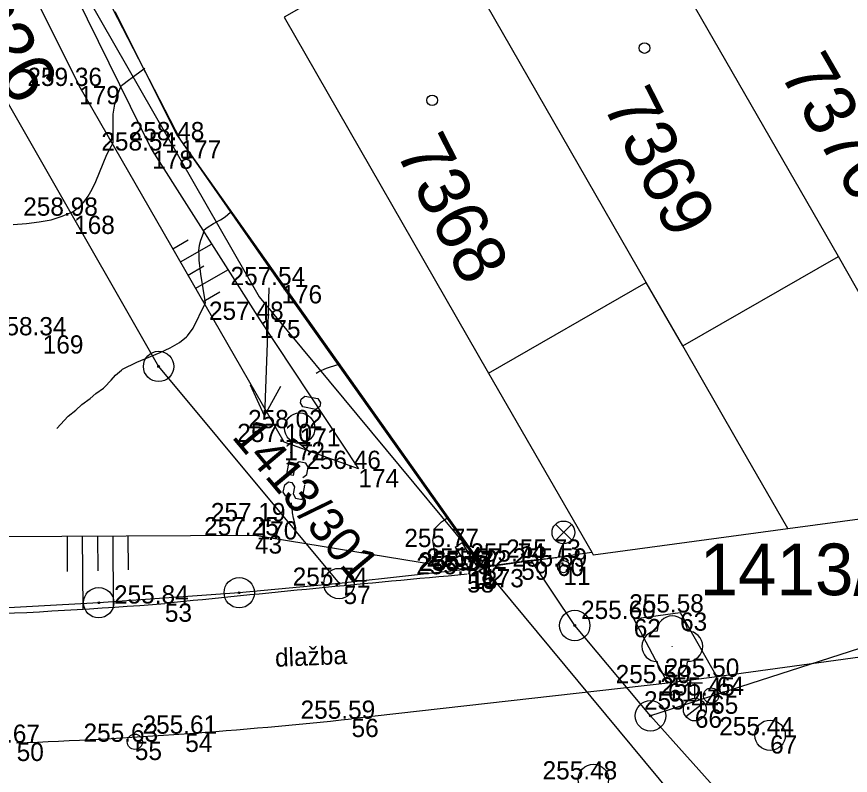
# Model space of a CAD drawing. Extents: x -771260 to -770828, y -1053564 to -1052811.
# Drawn here: x -770891.96 to -770864.55, y -1053372.8 to -1053347.85 of the extents above; entities that cross this region are included whole.
import ezdxf

# ---------------------------------------------------------------- set-up
doc = ezdxf.new("R2010")
doc.units = 0
for name, color, linetype in [('14_8_2023_asfalt', 7, 'Continuous'), ('14_8_2023_dlazba', 7, 'Continuous'), ('14_8_2023_hydrant_podzemni', 7, 'Continuous'), ('14_8_2023_lampa', 7, 'Continuous'), ('14_8_2023_plot', 7, 'Continuous'), ('14_8_2023_popis_povrchu', 7, 'Continuous'), ('14_8_2023_priska', 7, 'Continuous'), ('14_8_2023_sachta', 7, 'Continuous'), ('14_8_2023_soupe', 7, 'Continuous'), ('14_8_2023_strom', 7, 'Continuous'), ('14_8_2023_ter_hrana', 7, 'Continuous'), ('14_8_2023_ter_srafy', 7, 'Continuous'), ('14_8_2023_vstup_na_pozemek', 7, 'Continuous'), ('14_8_2023_zamereny_bod', 7, 'Continuous'), ('14_8_2023_zamereny_bod_cislo', 7, 'Continuous'), ('14_8_2023_zamereny_bod_vyska', 7, 'Continuous'), ('18_8_2023_plot', 7, 'Continuous'), ('18_8_2023_sachta', 7, 'Continuous'), ('18_8_2023_ter_hrana', 7, 'Continuous'), ('18_8_2023_ter_pata', 7, 'Continuous'), ('18_8_2023_ter_srafa', 7, 'Continuous'), ('18_8_2023_vrstevnice_po_1m', 7, 'Continuous'), ('18_8_2023_zamereny_bod', 7, 'Continuous'), ('18_8_2023_zamereny_bod_cislo', 7, 'Continuous'), ('18_8_2023_zamereny_bod_vyska', 7, 'Continuous'), ('DKM_Hranice parcel', 7, 'Continuous'), ('DKM_Parcelní čísla', 7, 'Continuous'), ('DKM_Pop  PČ popisy', 7, 'Continuous'), ('DKM_Vnitřní kresba', 7, 'Continuous'), ('DKM_Značky bodu BP', 7, 'Continuous'), ('DKM_Značky budov', 7, 'Continuous')]:
    doc.layers.add(name, color=color, linetype=linetype)

msp = doc.modelspace()

# ---------------------------------------------------------------- linework, layer by layer
at = {"layer": '14_8_2023_asfalt'}
msp.add_line((-770858.13, -1053368.076), (-770868.937, -1053369.555), dxfattribs=at)
at = {"layer": '14_8_2023_dlazba'}
for p, q in [((-770871.67, -1053367.654), (-770870.148, -1053367.441)), ((-770870.148, -1053367.441), (-770868.937, -1053369.555)), ((-770870.548, -1053369.768), (-770871.67, -1053367.654)), ((-770868.937, -1053369.555), (-770870.548, -1053369.768)), ((-770870.548, -1053369.768), (-770880.948, -1053370.937))]:
    msp.add_line(p, q, dxfattribs=at)
for centre, radius, start, end in [((-770800.804, -1054206.583), 843.858, 95.190639, 95.868492), ((-770900.926, -1053186.023), 181.652, 270.19912, 274.36998), ((-770897.564, -1053216.299), 155.529, 272.06585, 276.13275)]:
    msp.add_arc(centre, radius, start, end, dxfattribs=at)
at = {"layer": '14_8_2023_hydrant_podzemni'}
for p, q in [((-770869.912, -1053369.757), (-770869.412, -1053369.757)), ((-770869.662, -1053370.257), (-770869.662, -1053369.757)), ((-770869.956, -1053370.863), (-770869.366, -1053370.4))]:
    msp.add_line(p, q, dxfattribs=at)
msp.add_circle((-770869.662, -1053370.632), 0.375, dxfattribs=at)
at = {"layer": '14_8_2023_lampa'}
for p, q in [((-770874.246, -1053365.071), (-770873.718, -1053364.543)), ((-770873.71, -1053365.068), (-770874.238, -1053364.539)), ((-770873.982, -1053365.733), (-770873.982, -1053365.183))]:
    msp.add_line(p, q, dxfattribs=at)
for centre, radius in [((-770873.982, -1053364.808), 0.375), ((-770873.982, -1053365.933), 0.2)]:
    msp.add_circle(centre, radius, dxfattribs=at)
at = {"layer": '14_8_2023_plot'}
msp.add_line((-770876.674, -1053365.942), (-770875.371, -1053365.768), dxfattribs=at)
at = {"layer": '14_8_2023_priska'}
for p, q in [((-770877.541, -1053365.29), (-770877.311, -1053365.144)), ((-770877.541, -1053365.29), (-770877.046, -1053366.072)), ((-770876.816, -1053365.926), (-770877.311, -1053365.144)), ((-770877.046, -1053366.072), (-770876.816, -1053365.926))]:
    msp.add_line(p, q, dxfattribs=at)
at = {"layer": '14_8_2023_sachta'}
for centre in [(-770867.187, -1053371.48), (-770872.996, -1053372.932)]:
    msp.add_circle(centre, 0.5, dxfattribs=at)
at = {"layer": '14_8_2023_soupe'}
for centre in [(-770869.127, -1053370.173), (-770888.072, -1053371.693)]:
    msp.add_circle(centre, 0.25, dxfattribs=at)
at = {"layer": '14_8_2023_strom'}
msp.add_circle((-770870.404, -1053368.554), 0.0005, dxfattribs=at)
for centre, start, end in [((-770870.404, -1053368.054), 0, 180), ((-770870.904, -1053368.554), 90, 270), ((-770869.904, -1053368.554), 270, 90), ((-770870.404, -1053369.054), 180, 360)]:
    msp.add_arc(centre, 0.5, start, end, dxfattribs=at)
at = {"layer": '14_8_2023_ter_hrana'}
for p, q in [((-770884.123, -1053364.905), (-770897.467, -1053364.98)), ((-770877.079, -1053366.064), (-770884.123, -1053364.905))]:
    msp.add_line(p, q, dxfattribs=at)
at = {"layer": '14_8_2023_ter_srafy'}
for p, q in [((-770890.3, -1053364.939), (-770890.293, -1053366.098)), ((-770889.8, -1053364.936), (-770889.786, -1053367.333)), ((-770889.3, -1053364.934), (-770889.293, -1053366.067)), ((-770888.8, -1053364.931), (-770888.786, -1053367.269)), ((-770888.3, -1053364.928), (-770888.293, -1053366.036))]:
    msp.add_line(p, q, dxfattribs=at)
at = {"layer": '14_8_2023_vstup_na_pozemek'}
msp.add_line((-770874.194, -1053365.641), (-770875.371, -1053365.768), dxfattribs=at)
at = {"layer": '14_8_2023_zamereny_bod'}
for p, q in [((-770884.123, -1053364.905), (-770884.123, -1053364.905)), ((-770877.541, -1053365.29), (-770877.541, -1053365.29)), ((-770875.371, -1053365.768), (-770875.371, -1053365.768)), ((-770874.194, -1053365.641), (-770874.194, -1053365.641)), ((-770877.079, -1053366.064), (-770877.079, -1053366.064)), ((-770877.046, -1053366.072), (-770877.046, -1053366.072)), ((-770876.812, -1053365.934), (-770876.812, -1053365.934)), ((-770873.982, -1053365.933), (-770873.982, -1053365.933)), ((-770877.148, -1053366.185), (-770877.148, -1053366.185)), ((-770881.211, -1053366.564), (-770881.211, -1053366.564)), ((-770887.085, -1053367.147), (-770887.085, -1053367.147)), ((-770870.148, -1053367.441), (-770870.148, -1053367.441)), ((-770871.67, -1053367.654), (-770871.67, -1053367.654)), ((-770868.937, -1053369.555), (-770868.937, -1053369.555)), ((-770870.548, -1053369.768), (-770870.548, -1053369.768)), ((-770869.127, -1053370.173), (-770869.127, -1053370.173)), ((-770869.662, -1053370.632), (-770869.662, -1053370.632)), ((-770880.948, -1053370.937), (-770880.948, -1053370.937)), ((-770886.415, -1053371.427), (-770886.415, -1053371.427)), ((-770867.187, -1053371.48), (-770867.187, -1053371.48)), ((-770888.072, -1053371.693), (-770888.072, -1053371.693))]:
    msp.add_line(p, q, dxfattribs=at)
at = {"layer": '18_8_2023_plot'}
for p, q in [((-770889.236, -1053346.745), (-770886.57, -1053351.912)), ((-770886.57, -1053351.912), (-770883.254, -1053356.677)), ((-770883.254, -1053356.677), (-770876.674, -1053365.942))]:
    msp.add_line(p, q, dxfattribs=at)
at = {"layer": '18_8_2023_sachta'}
msp.add_circle((-770882.652, -1053361.381), 0.5, dxfattribs=at)
at = {"layer": '18_8_2023_ter_hrana'}
for p, q in [((-770894.318, -1053341.233), (-770889.903, -1053350.127)), ((-770883.159, -1053361.835), (-770889.903, -1053350.127)), ((-770880.721, -1053362.721), (-770883.159, -1053361.835))]:
    msp.add_line(p, q, dxfattribs=at)
at = {"layer": '18_8_2023_ter_pata'}
for p, q in [((-770887.502, -1053352.25), (-770890.436, -1053346.273)), ((-770887.502, -1053352.25), (-770883.963, -1053357.819)), ((-770883.963, -1053357.819), (-770880.721, -1053362.721))]:
    msp.add_line(p, q, dxfattribs=at)
at = {"layer": '18_8_2023_ter_srafa'}
for p, q in [((-770886.819, -1053355.48), (-770886.317, -1053355.191)), ((-770886.569, -1053355.913), (-770885.547, -1053355.324)), ((-770886.32, -1053356.346), (-770885.799, -1053356.047)), ((-770886.07, -1053356.78), (-770885.011, -1053356.169)), ((-770885.821, -1053357.213), (-770885.281, -1053356.902))]:
    msp.add_line(p, q, dxfattribs=at)
at = {"layer": '18_8_2023_vrstevnice_po_1m'}
for points in [[(-770892.071, -1053354.686), (-770891.633, -1053354.654), (-770891.216, -1053354.6), (-770890.82, -1053354.524), (-770890.459, -1053354.41), (-770890.254, -1053354.32), (-770890.145, -1053354.273), (-770890.105, -1053354.255), (-770890.061, -1053354.223), (-770889.877, -1053354.089), (-770889.748, -1053353.952), (-770889.602, -1053353.75), (-770889.473, -1053353.52), (-770889.355, -1053353.268), (-770888.988, -1053352.38), (-770888.843, -1053352.091), (-770888.807, -1053352.03), (-770888.782, -1053351.987), (-770888.784, -1053351.116), (-770888.784, -1053351.056), (-770888.731, -1053350.723), (-770888.665, -1053350.485), (-770888.567, -1053350.234), (-770888.529, -1053350.158), (-770888.506, -1053350.11), (-770888.241, -1053349.905), (-770888.208, -1053349.879), (-770887.781, -1053349.566), (-770887.746, -1053349.54)], [(-770887.746, -1053349.54), (-770887.746, -1053349.54)], [(-770887.746, -1053349.54), (-770887.746, -1053349.54)], [(-770888.208, -1053349.879), (-770888.208, -1053349.879)], [(-770888.506, -1053350.11), (-770888.506, -1053350.11)], [(-770888.665, -1053350.485), (-770888.665, -1053350.485)], [(-770888.567, -1053350.234), (-770888.567, -1053350.234)], [(-770888.731, -1053350.723), (-770888.731, -1053350.723)], [(-770888.784, -1053351.056), (-770888.784, -1053351.056)], [(-770888.843, -1053352.091), (-770888.843, -1053352.091)], [(-770888.782, -1053351.987), (-770888.782, -1053351.987)], [(-770888.988, -1053352.38), (-770888.988, -1053352.38)], [(-770889.355, -1053353.268), (-770889.355, -1053353.268)], [(-770889.602, -1053353.75), (-770889.602, -1053353.75)], [(-770889.473, -1053353.52), (-770889.473, -1053353.52)], [(-770889.748, -1053353.952), (-770889.748, -1053353.952)], [(-770890.64, -1053361.388), (-770890.259, -1053360.983), (-770890.011, -1053360.786), (-770889.815, -1053360.607), (-770889.542, -1053360.408), (-770889.352, -1053360.239), (-770889.103, -1053360.064), (-770889.065, -1053360.037), (-770888.846, -1053359.802), (-770888.712, -1053359.637), (-770888.512, -1053359.471), (-770888.475, -1053359.441), (-770888.007, -1053359.209), (-770887.235, -1053358.893), (-770886.907, -1053358.742), (-770886.602, -1053358.566), (-770886.374, -1053358.373), (-770886.339, -1053358.344), (-770886.16, -1053358.093), (-770885.767, -1053357.307), (-770885.744, -1053357.26), (-770885.901, -1053356.318), (-770885.954, -1053355.857), (-770885.959, -1053355.654), (-770885.963, -1053355.547), (-770885.945, -1053355.361), (-770885.906, -1053355.193), (-770885.82, -1053354.965), (-770885.806, -1053354.918), (-770885.79, -1053354.863), (-770885.697, -1053354.783), (-770885.481, -1053354.647), (-770885.295, -1053354.55), (-770885.253, -1053354.529), (-770885.101, -1053354.426), (-770884.922, -1053354.279), (-770884.888, -1053354.251)], [(-770890.105, -1053354.255), (-770890.105, -1053354.255)], [(-770889.877, -1053354.089), (-770889.877, -1053354.089)], [(-770884.888, -1053354.251), (-770884.888, -1053354.251)], [(-770884.888, -1053354.251), (-770884.888, -1053354.251)], [(-770891.216, -1053354.6), (-770891.216, -1053354.6)], [(-770890.82, -1053354.524), (-770890.82, -1053354.524)], [(-770890.459, -1053354.41), (-770890.459, -1053354.41)], [(-770885.253, -1053354.529), (-770885.253, -1053354.529)], [(-770885.101, -1053354.426), (-770885.101, -1053354.426)], [(-770891.633, -1053354.654), (-770891.633, -1053354.654)], [(-770885.79, -1053354.863), (-770885.79, -1053354.863)], [(-770885.697, -1053354.783), (-770885.697, -1053354.783)], [(-770885.481, -1053354.647), (-770885.481, -1053354.647)], [(-770885.82, -1053354.965), (-770885.82, -1053354.965)], [(-770885.945, -1053355.361), (-770885.945, -1053355.361)], [(-770885.906, -1053355.193), (-770885.906, -1053355.193)], [(-770885.963, -1053355.547), (-770885.963, -1053355.547)], [(-770885.954, -1053355.857), (-770885.954, -1053355.857)], [(-770885.901, -1053356.318), (-770885.901, -1053356.318)], [(-770885.744, -1053357.26), (-770885.744, -1053357.26)], [(-770886.16, -1053358.093), (-770886.16, -1053358.093)], [(-770886.339, -1053358.344), (-770886.339, -1053358.344)], [(-770886.602, -1053358.566), (-770886.602, -1053358.566)], [(-770887.235, -1053358.893), (-770887.235, -1053358.893)], [(-770886.907, -1053358.742), (-770886.907, -1053358.742)], [(-770888.007, -1053359.209), (-770888.007, -1053359.209)], [(-770888.475, -1053359.441), (-770888.475, -1053359.441)], [(-770882.114, -1053359.574), (-770882.056, -1053359.536), (-770882.021, -1053359.514), (-770881.775, -1053359.411), (-770881.397, -1053359.291), (-770881.353, -1053359.277)], [(-770882.021, -1053359.514), (-770882.021, -1053359.514)], [(-770881.775, -1053359.411), (-770881.775, -1053359.411)], [(-770888.846, -1053359.802), (-770888.846, -1053359.802)], [(-770888.712, -1053359.637), (-770888.712, -1053359.637)], [(-770882.114, -1053359.574), (-770882.114, -1053359.574)], [(-770889.065, -1053360.037), (-770889.065, -1053360.037)], [(-770889.352, -1053360.239), (-770889.352, -1053360.239)], [(-770881.99, -1053360.665), (-770882.119, -1053360.762), (-770882.547, -1053360.681), (-770882.631, -1053360.543), (-770882.609, -1053360.425), (-770882.479, -1053360.328), (-770882.052, -1053360.409), (-770881.967, -1053360.547), (-770881.99, -1053360.665)], [(-770889.815, -1053360.607), (-770889.815, -1053360.607)], [(-770889.542, -1053360.408), (-770889.542, -1053360.408)], [(-770890.011, -1053360.786), (-770890.011, -1053360.786)], [(-770890.259, -1053360.983), (-770890.259, -1053360.983)], [(-770890.64, -1053361.388), (-770890.64, -1053361.388)], [(-770882.124, -1053361.371), (-770882.231, -1053361.35)], [(-770882.945, -1053362.189), (-770882.855, -1053361.719), (-770882.281, -1053362.194)], [(-770882.544, -1053362.997), (-770882.415, -1053362.899), (-770882.37, -1053362.664), (-770882.455, -1053362.526), (-770882.669, -1053362.486), (-770882.798, -1053362.583), (-770882.865, -1053362.936), (-770883.079, -1053362.895), (-770882.989, -1053362.424)], [(-770883.106, -1053363.621), (-770883.191, -1053363.483), (-770883.146, -1053363.248), (-770883.017, -1053363.15), (-770882.91, -1053363.171), (-770882.825, -1053363.309), (-770882.87, -1053363.544), (-770882.786, -1053363.682), (-770882.572, -1053363.723), (-770882.482, -1053363.252)], [(-770882.806, -1053364.668), (-770882.816, -1053364.507), (-770882.856, -1053364.342), (-770882.886, -1053364.166), (-770882.898, -1053364.001), (-770882.923, -1053363.853), (-770882.926, -1053363.838)], [(-770882.898, -1053364.001), (-770882.898, -1053364.001)], [(-770882.886, -1053364.166), (-770882.886, -1053364.166)], [(-770882.856, -1053364.342), (-770882.856, -1053364.342)], [(-770878.164, -1053365.649), (-770878.183, -1053365.584), (-770878.27, -1053365.073), (-770878.215, -1053364.734), (-770878.206, -1053364.684), (-770877.99, -1053364.456), (-770877.891, -1053364.399), (-770877.814, -1053364.336), (-770877.78, -1053364.308)], [(-770877.99, -1053364.456), (-770877.99, -1053364.456)], [(-770877.891, -1053364.399), (-770877.891, -1053364.399)], [(-770877.78, -1053364.308), (-770877.78, -1053364.308)], [(-770877.78, -1053364.308), (-770877.78, -1053364.308)], [(-770882.816, -1053364.507), (-770882.816, -1053364.507)], [(-770882.806, -1053364.668), (-770882.806, -1053364.668)], [(-770878.206, -1053364.684), (-770878.206, -1053364.684)], [(-770878.27, -1053365.073), (-770878.27, -1053365.073)], [(-770878.183, -1053365.584), (-770878.183, -1053365.584)], [(-770878.164, -1053365.649), (-770878.164, -1053365.649)]]:
    msp.add_lwpolyline(points, dxfattribs=at)
at = {"layer": '18_8_2023_zamereny_bod'}
for p, q in [((-770889.903, -1053350.127), (-770889.903, -1053350.127)), ((-770886.57, -1053351.912), (-770886.57, -1053351.912)), ((-770887.502, -1053352.25), (-770887.502, -1053352.25)), ((-770890.068, -1053354.394), (-770890.068, -1053354.394)), ((-770883.254, -1053356.677), (-770883.254, -1053356.677)), ((-770883.963, -1053357.819), (-770883.963, -1053357.819)), ((-770891.101, -1053358.327), (-770891.101, -1053358.327)), ((-770882.652, -1053361.381), (-770882.652, -1053361.381)), ((-770883.159, -1053361.835), (-770883.159, -1053361.835)), ((-770880.721, -1053362.721), (-770880.721, -1053362.721)), ((-770884.067, -1053364.441), (-770884.067, -1053364.441)), ((-770876.623, -1053366.013), (-770876.623, -1053366.013))]:
    msp.add_line(p, q, dxfattribs=at)
at = {"layer": 'DKM_Hranice parcel'}
for p, q in [((-770891.21, -1053344.44), (-770883.99, -1053357.06)), ((-770886.69, -1053351.72), (-770888.72, -1053347.69)), ((-770876.6, -1053365.96), (-770886.69, -1053351.72)), ((-770883.99, -1053357.06), (-770876.6, -1053365.96)), ((-770841.15, -1053361.17), (-770871.12, -1053370.84)), ((-770866.61, -1053364.68), (-770860.3, -1053363.83)), ((-770875.03, -1053365.74), (-770873.05, -1053365.46)), ((-770875.03, -1053365.74), (-770876.6, -1053365.96)), ((-770876.6, -1053365.96), (-770881.36, -1053366.49)), ((-770865.26, -1053379.61), (-770876.6, -1053365.96))]:
    msp.add_line(p, q, dxfattribs=at)
for points in [[(-770902.17, -1053333.34), (-770887.29, -1053359.35), (-770881.36, -1053366.49)], [(-770877.98, -1053344.89), (-770883.16, -1053347.86), (-770876.44, -1053359.57), (-770873.05, -1053365.46)], [(-770860.3, -1053363.83), (-770862.54, -1053359.93), (-770863.75, -1053357.82), (-770864.94, -1053355.74), (-770870.47, -1053346.11)], [(-770866.61, -1053364.68), (-770868.29, -1053361.75), (-770870.06, -1053358.67), (-770871.26, -1053356.59), (-770876.78, -1053346.97)], [(-770873.05, -1053365.46), (-770873, -1053365.55), (-770866.61, -1053364.68)], [(-770871.12, -1053370.84), (-770873.61, -1053367.87), (-770875.03, -1053365.74)], [(-770881.36, -1053366.49), (-770884.64, -1053366.79), (-770889.26, -1053367.12), (-770893.63, -1053367.36)], [(-770863.65, -1053379.42), (-770866.27, -1053376.27), (-770871.12, -1053370.84)]]:
    msp.add_lwpolyline(points, dxfattribs=at)
at = {"layer": 'DKM_Pop  PČ popisy'}
for p, q in [((-770883.67, -1053356.76), (-770883.7, -1053357.98)), ((-770883.7, -1053357.98), (-770883.805, -1053360.979)), ((-770883.805, -1053360.979), (-770884.27, -1053359.961)), ((-770883.805, -1053360.979), (-770883.269, -1053359.996))]:
    msp.add_line(p, q, dxfattribs=at)
at = {"layer": 'DKM_Vnitřní kresba'}
for p, q in [((-770870.06, -1053358.67), (-770864.94, -1053355.74)), ((-770876.44, -1053359.57), (-770871.26, -1053356.59))]:
    msp.add_line(p, q, dxfattribs=at)
at = {"layer": 'DKM_Značky bodu BP'}
for centre, radius in [((-770887.29, -1053359.35), 0.5), ((-770887.29, -1053359.35), 0.0303), ((-770881.36, -1053366.49), 0.5), ((-770884.64, -1053366.79), 0.5), ((-770889.26, -1053367.12), 0.5), ((-770881.36, -1053366.49), 0.0303), ((-770884.64, -1053366.79), 0.0303), ((-770889.26, -1053367.12), 0.0303), ((-770873.61, -1053367.87), 0.5), ((-770873.61, -1053367.87), 0.0303), ((-770871.12, -1053370.84), 0.5), ((-770871.12, -1053370.84), 0.0303)]:
    msp.add_circle(centre, radius, dxfattribs=at)
at = {"layer": 'DKM_Značky budov'}
for centre in [(-770871.317, -1053348.879), (-770878.297, -1053350.599)]:
    msp.add_circle(centre, 0.175, dxfattribs=at)

# ---------------------------------------------------------------- texts
at = {"layer": '14_8_2023_popis_povrchu'}
msp.add_text('dlažba', height=0.6, rotation=2.3434, dxfattribs=at).set_placement((-770883.452, -1053369.229))
at = {"layer": '14_8_2023_zamereny_bod_cislo'}
for s, p in [('43', (-770884.123, -1053365.505)), ('14', (-770877.541, -1053365.89)), ('59', (-770875.371, -1053366.368)), ('60', (-770874.194, -1053366.241)), ('15', (-770877.079, -1053366.664)), ('13', (-770877.046, -1053366.672)), ('12', (-770876.812, -1053366.534)), ('11', (-770873.982, -1053366.533)), ('58', (-770877.148, -1053366.785)), ('57', (-770881.211, -1053367.164)), ('53', (-770887.085, -1053367.747)), ('63', (-770870.148, -1053368.041)), ('62', (-770871.67, -1053368.254)), ('64', (-770868.937, -1053370.155)), ('61', (-770870.548, -1053370.368)), ('65', (-770869.127, -1053370.773)), ('66', (-770869.662, -1053371.232)), ('56', (-770880.948, -1053371.537)), ('54', (-770886.415, -1053372.027)), ('67', (-770867.187, -1053372.08)), ('50', (-770891.957, -1053372.326)), ('55', (-770888.072, -1053372.293))]:
    msp.add_text(s, height=0.6, dxfattribs=at).set_placement(p)
at = {"layer": '14_8_2023_zamereny_bod_vyska'}
for s, p in [('257.25 ', (-770885.795, -1053364.905)), ('255.77 ', (-770879.213, -1053365.29)), ('255.74 ', (-770877.043, -1053365.768)), ('255.73 ', (-770875.866, -1053365.641)), ('255.74 ', (-770878.751, -1053366.064)), ('255.57 ', (-770878.718, -1053366.072)), ('255.57 ', (-770878.484, -1053365.934)), ('255.59 ', (-770875.658, -1053365.933)), ('255.73 ', (-770878.82, -1053366.185)), ('255.74 ', (-770882.883, -1053366.564)), ('255.84 ', (-770888.757, -1053367.147)), ('255.58 ', (-770871.82, -1053367.441)), ('255.60 ', (-770873.402, -1053367.654)), ('255.50 ', (-770870.653, -1053369.555)), ('255.50 ', (-770872.264, -1053369.768)), ('255.45 ', (-770870.799, -1053370.173)), ('255.44 ', (-770871.334, -1053370.632)), ('255.59 ', (-770882.624, -1053370.937)), ('255.61 ', (-770887.82, -1053371.427)), ('255.44 ', (-770868.859, -1053371.48)), ('255.67 ', (-770893.645, -1053371.726)), ('255.63 ', (-770889.76, -1053371.693)), ('255.48 ', (-770874.668, -1053372.932))]:
    msp.add_text(s, height=0.6, dxfattribs=at).set_placement(p)
at = {"layer": '18_8_2023_zamereny_bod_cislo'}
for s, p in [('179', (-770889.903, -1053350.727)), ('177', (-770886.57, -1053352.512)), ('178', (-770887.502, -1053352.85)), ('168', (-770890.068, -1053354.994)), ('176', (-770883.254, -1053357.277)), ('175', (-770883.963, -1053358.419)), ('169', (-770891.101, -1053358.927)), ('171', (-770882.652, -1053361.981)), ('172', (-770883.159, -1053362.435)), ('174', (-770880.721, -1053363.321)), ('170', (-770884.067, -1053365.041)), ('173', (-770876.623, -1053366.613))]:
    msp.add_text(s, height=0.6, dxfattribs=at).set_placement(p)
at = {"layer": '18_8_2023_zamereny_bod_vyska'}
for s, p in [('259.36 ', (-770891.605, -1053350.127)), ('258.48 ', (-770888.242, -1053351.912)), ('258.54 ', (-770889.174, -1053352.25)), ('258.98 ', (-770891.742, -1053354.394)), ('257.54 ', (-770884.926, -1053356.677)), ('257.48 ', (-770885.635, -1053357.819)), ('258.34 ', (-770892.773, -1053358.327)), ('258.02 ', (-770884.35, -1053361.381)), ('257.10 ', (-770884.705, -1053361.835)), ('256.46 ', (-770882.437, -1053362.721)), ('257.19 ', (-770885.573, -1053364.441)), ('255.72 ', (-770878.295, -1053366.013))]:
    msp.add_text(s, height=0.6, dxfattribs=at).set_placement(p)
at = {"layer": 'DKM_Parcelní čísla'}
for s, height, rotation, p in [('1410/226', 1.7, 301, (-770896.86, -1053342.711)), ('7370', 1.7, 300, (-770866.903, -1053349.689)), ('7369', 1.7, 297, (-770872.717, -1053350.725)), ('7368', 1.7, 297, (-770879.517, -1053352.265)), ('1413/301', 1.139, 310, (-770884.915, -1053361.673))]:
    msp.add_text(s, height=height, rotation=rotation, dxfattribs=at).set_placement(p)
msp.add_text('1413/304', height=1.7, dxfattribs=at).set_placement((-770869.505, -1053366.873))

doc.saveas('drawing.dxf')
